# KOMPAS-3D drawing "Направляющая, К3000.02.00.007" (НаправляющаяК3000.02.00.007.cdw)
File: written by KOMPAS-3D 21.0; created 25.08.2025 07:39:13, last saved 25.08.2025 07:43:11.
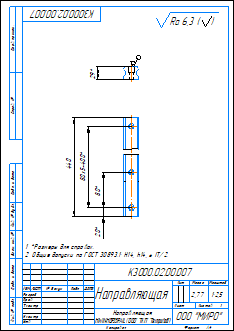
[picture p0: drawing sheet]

Sheet 1: A4, portrait

Document properties: Автор: admin; Полное имя файла: C:\Users\ShavarinML\Desktop\Стапель\2D\НаправляющаяК3000.02.00.007.cdw; Знак неуказанной шероховатости: 4; Параметр неуказанной шероховатости: Ra 6,3; Масса: 2.771005

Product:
- Part/product: Направляющая  | designation К3000.02.00.007
    Масса: 2.771005
  - Body: Тело 1
      Масса: 2.926069

Title block, sheet 1: Наименование: Направляющая; designation: К3000.02.00.007; Материал: Направляющая / HIWIN-HGR35RAIL ("ООО" "ТКП" "Техпривод"); Масса: 2,77; Количество листов документа: 1; organisation: ООО "МИРО"; Форматы листов документа: A4

Views: Спереди 1, Спереди, Проекционный вид 2
Referenced files in C:\Users\ShavarinML\Desktop\Стапель\Задняя бабака\Направляющие\Профильные направляющие HIWIN\: HGR35RAIL.m3d
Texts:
  Ra 6,3
  Ra 6,3 ( )
  К3000.02.00.007 Направляющая
Dimensions and other numbers on the sheet: 29; 440; 20; 80; 80х5=400; 1:2,5; 1; 2,77

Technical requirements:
  *Размеры для справок.
  Общие допуски по ГОСТ 30893.1: H14, h14,   IT/2.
